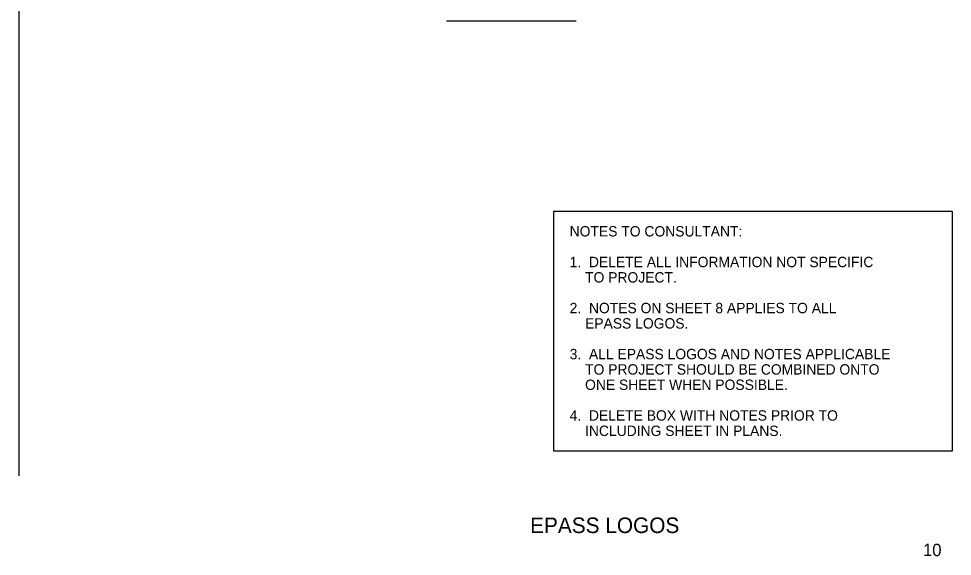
# Model space of a CAD drawing. Extents: x 10268197 to 10268826, y 2141503 to 2142677.
# Drawn here: x 10268664.3 to 10268739.3, y 2142329.1 to 2142372.3 of the extents above; entities that cross this region are included whole.
import ezdxf

# ---------------------------------------------------------------- set-up
doc = ezdxf.new("R2010")
doc.units = 0
for name, color, linetype in [('NonPlottingEle_dp', 7, 'Continuous'), ('TextAlert', 7, 'Continuous'), ('TextDetails', 7, 'Continuous'), ('TextMisc', 7, 'Continuous'), ('TextShtNo', 7, 'Continuous')]:
    doc.layers.add(name, color=color, linetype=linetype)

msp = doc.modelspace()

# ---------------------------------------------------------------- linework, layer by layer
at = {"layer": 'NonPlottingEle_dp'}
msp.add_line((10268664.322, 2142431.588), (10268664.322, 2142335.588), dxfattribs=at)
at = {"layer": 'TextAlert'}
msp.add_lwpolyline([(10268707.308, 2142356.875), (10268739.323, 2142356.875), (10268739.323, 2142337.588), (10268707.308, 2142337.588)], close=True, dxfattribs=at)
at = {"layer": 'TextDetails'}
msp.add_line((10268698.678, 2142372.174), (10268709.11, 2142372.174), dxfattribs=at)

# ---------------------------------------------------------------- texts
at = {"layer": 'TextAlert'}
for s, p in [('NOTES TO CONSULTANT:', (10268708.584, 2142354.831)), ('1.  DELETE ALL INFORMATION NOT SPECIFIC ', (10268708.584, 2142352.365)), ('    TO PROJECT.', (10268708.584, 2142351.131)), ('2.  NOTES ON SHEET 8 APPLIES TO ALL ', (10268708.584, 2142348.665)), ('    EPASS LOGOS.', (10268708.584, 2142347.431)), ('3.  ALL EPASS LOGOS AND NOTES APPLICABLE', (10268708.584, 2142344.965)), ('    TO PROJECT SHOULD BE COMBINED ONTO', (10268708.584, 2142343.731)), ('    ONE SHEET WHEN POSSIBLE.', (10268708.584, 2142342.498)), ('4.  DELETE BOX WITH NOTES PRIOR TO ', (10268708.584, 2142340.031)), ('    INCLUDING SHEET IN PLANS.', (10268708.584, 2142338.798))]:
    msp.add_text(s, height=0.83333, dxfattribs=at).set_placement(p)
at = {"layer": 'TextMisc'}
msp.add_text('         EPASS LOGOS           ', height=1.25, rotation=360, dxfattribs=at).set_placement((10268701.228, 2142330.996))
at = {"layer": 'TextShtNo'}
msp.add_text('10', height=1, rotation=360, dxfattribs=at).set_placement((10268736.967, 2142329.139))

doc.saveas('drawing.dxf')
